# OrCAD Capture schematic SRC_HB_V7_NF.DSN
size A3; title: LMG3410R150; rev: 1.0; note: *
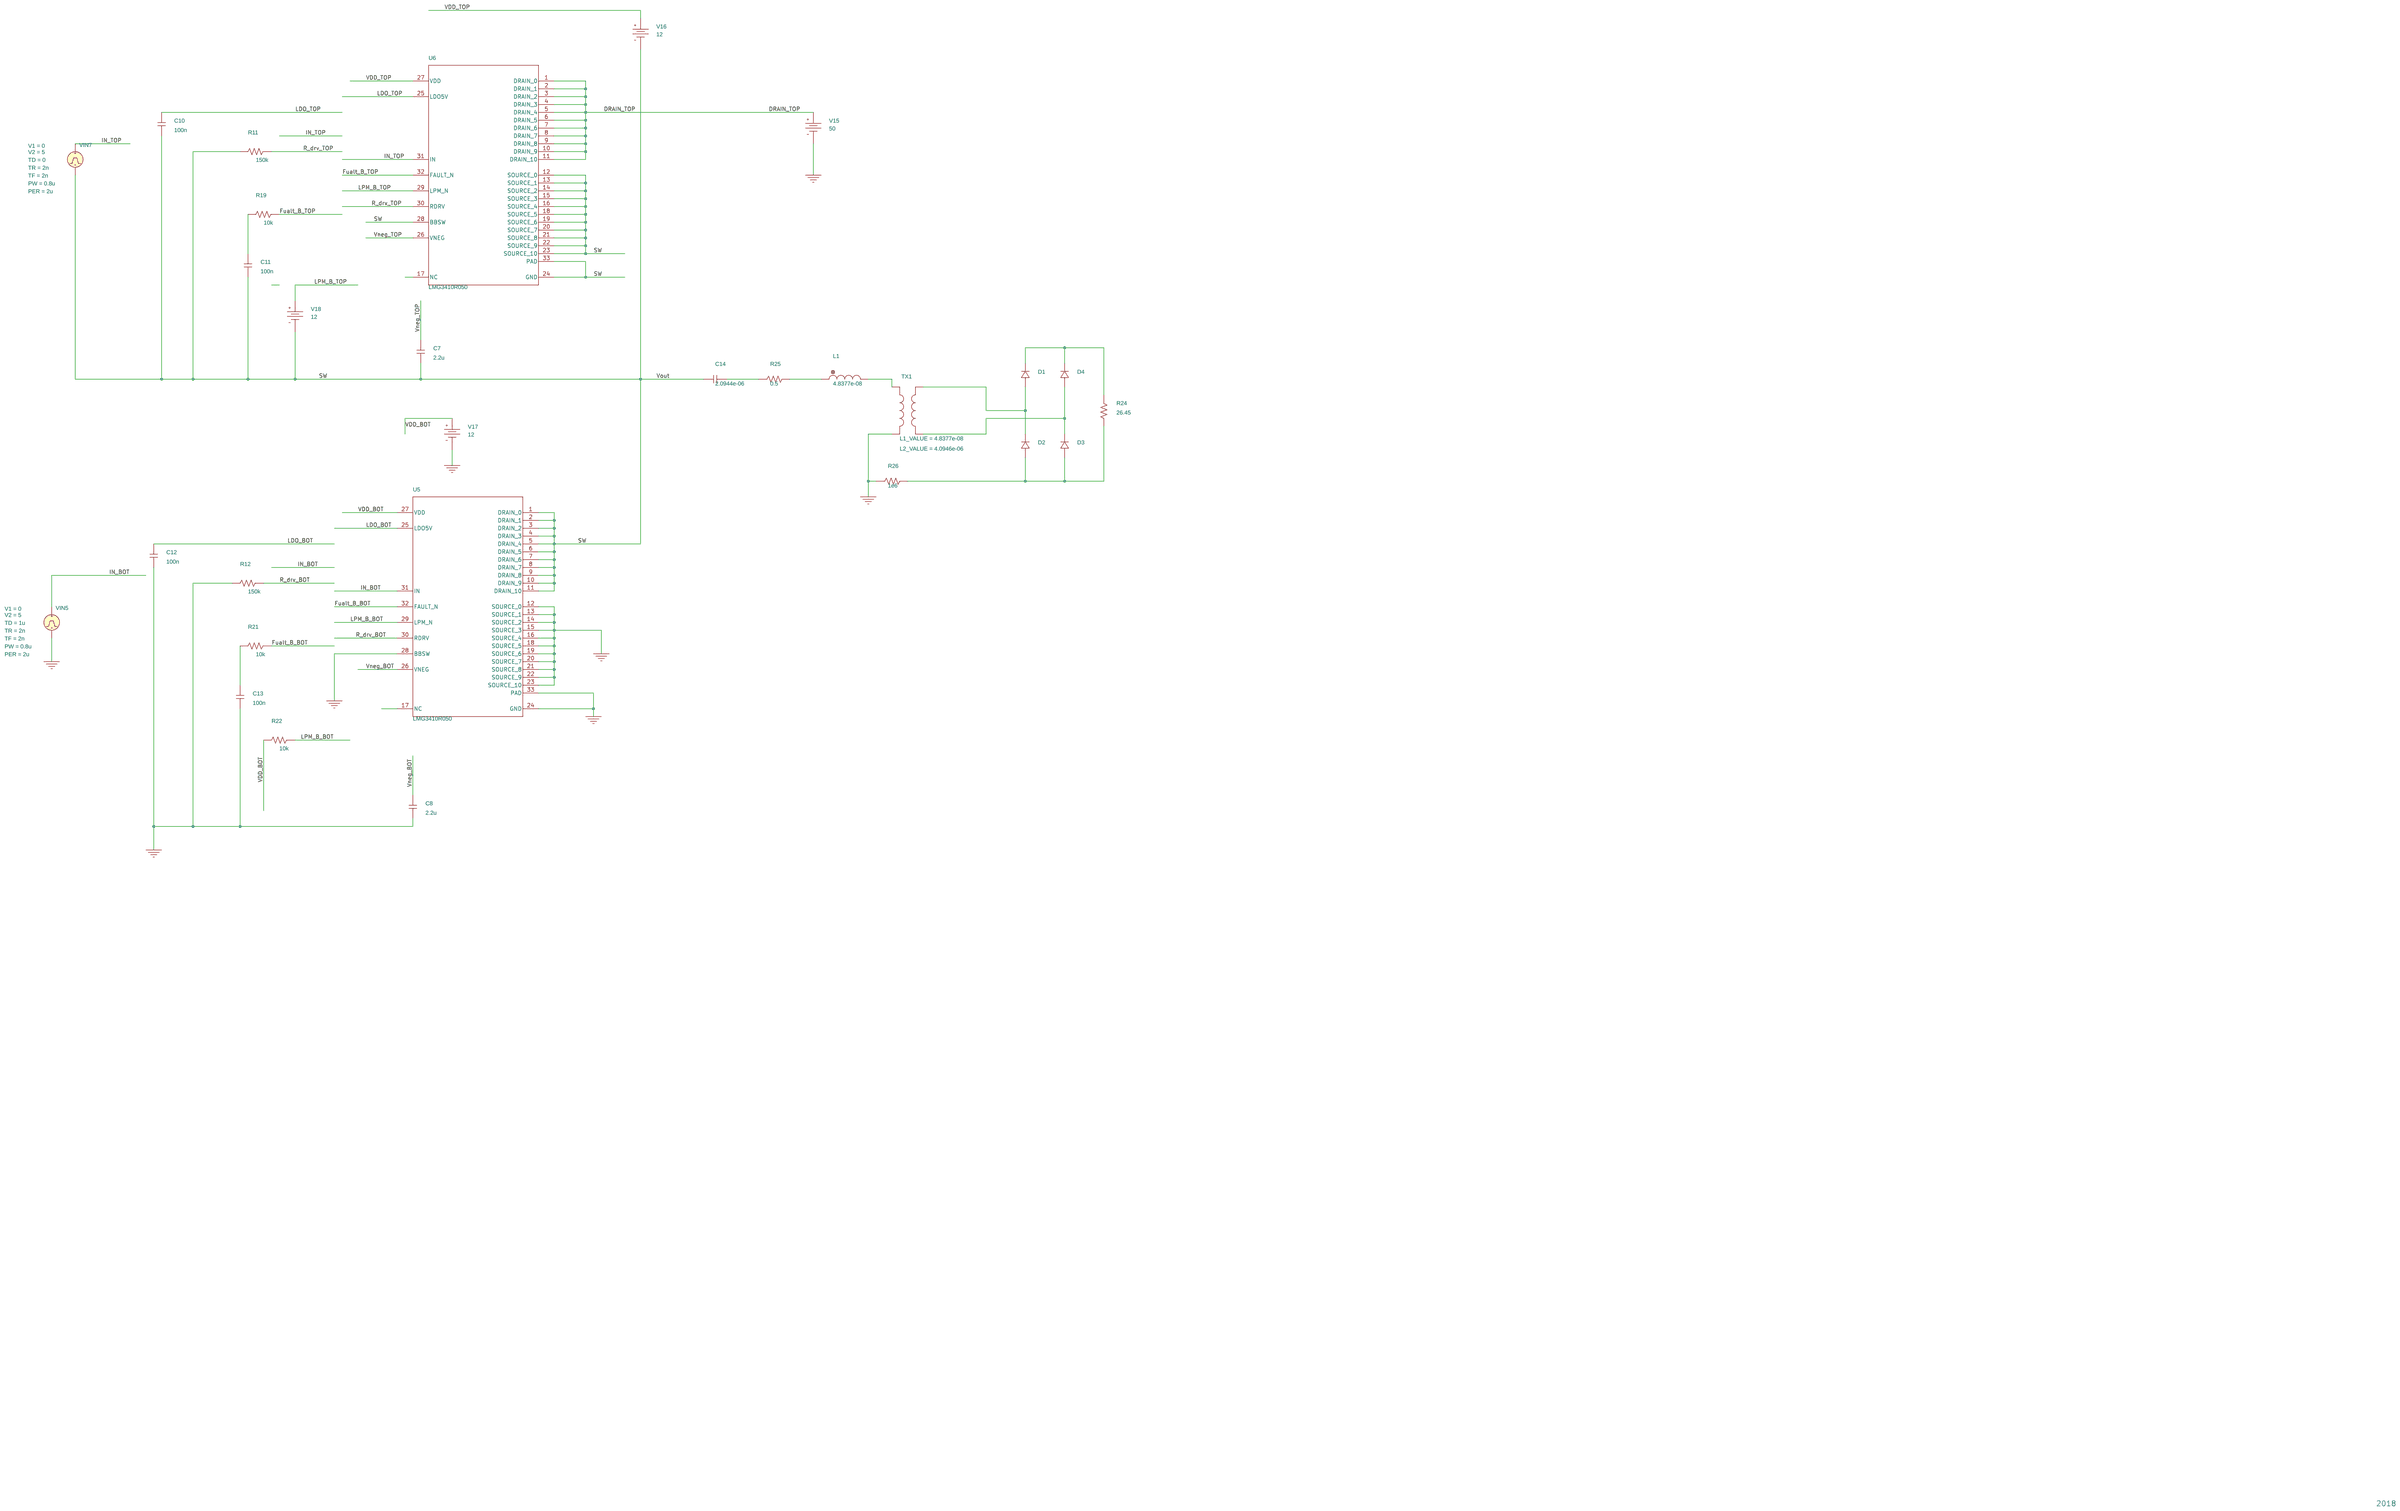
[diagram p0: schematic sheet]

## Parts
C7  2.2u  [RAD/CK05]
C8  2.2u  [RAD/CK05]
C10  100n  [RAD/CK05]
C11  100n  [RAD/CK05]
C12  100n  [RAD/CK05]
C13  100n  [RAD/CK05]
C14  2.0944e-06  [RAD/CK05]
D1  Dbreak
D2  Dbreak
D3  Dbreak
D4  Dbreak
L1  4.8377e-08  [DISC/.350x.175/LS.200x.100/.034]
R11  150k  [AX/RC05]
R12  150k  [AX/RC05]
R19  10k  [AX/RC05]
R21  10k  [AX/RC05]
R22  10k  [AX/RC05]
R24  26.45  [AX/RC05]
R25  0.5  [AX/RC05]
R26  1e6  [AX/RC05]
TX1  XFRM_LINEAR
U5  LMG3410R050  [RWH0032A]
U6  LMG3410R050  [RWH0032A]
V15  VDC
V16  VDC
V17  VDC
V18  VDC
VIN5  VPULSE
VIN7  VPULSE

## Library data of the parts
C7 C8 C10-C14 = C
D1-D4 = Dbreak
L1 = L
R11 R12 R19 R21 R22 R24-R26 = R
TX1 = XFRM_LINEAR: L1_VALUE: 4.8377e-08; L2_VALUE: 4.0946e-06
U5 U6 = LMG3410R050: Testbenches: [{"TestbenchDisplayName": "LMG3410R050 PSpice unencrypted model", "TestbenchURL": "https://software-dl.ti.com/pspice/esd/models/lmg3410r050_V1.0.zip", "TestbenchOpj": "LMG3410R050/lmg3410r050.opj"}]; Version: 1; productURL: http://www.ti.com/document-viewer/LMG3410R050/datasheet/
V15 = VDC: DC: 50
V16-V18 = VDC: DC: 12
VIN5 = VPULSE: PER: 2u; PW: 0.8u; TD: 1u; TF: 2n; TR: 2n; V1: 0; V2: 5
VIN7 = VPULSE: PER: 2u; PW: 0.8u; TD: 0; TF: 2n; TR: 2n; V1: 0; V2: 5

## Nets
VDD_BOT: R22.2 U5.27(VDD) V17.0(+)
VDD_TOP: U6.27(VDD) V16.0(+)
0: C8.1 C12.1 C13.1 R12.2 R26.1 TX1.2 U5.12(SOURCE_0) U5.13(SOURCE_1) U5.14(SOURCE_2) U5.15(SOURCE_3) U5.16(SOURCE_4) U5.18(SOURCE_5) U5.19(SOURCE_6) U5.20(SOURCE_7) U5.21(SOURCE_8) U5.22(SOURCE_9) U5.23(SOURCE_10) U5.24(GND) U5.28(BBSW) U5.33(PAD) V15.1(-) V17.1(-) VIN5.2(-)
DRAIN_TOP: U6.1(DRAIN_0) U6.2(DRAIN_1) U6.3(DRAIN_2) U6.4(DRAIN_3) U6.5(DRAIN_4) U6.6(DRAIN_5) U6.7(DRAIN_6) U6.8(DRAIN_7) U6.9(DRAIN_8) U6.10(DRAIN_9) U6.11(DRAIN_10) V15.0(+)
Fualt_B_BOT: R21.1 U5.32(FAULT_N)
Fualt_B_TOP: R19.1 U6.32(FAULT_N)
IN_BOT: U5.31(IN) VIN5.1(+)
IN_TOP: U6.31(IN) VIN7.1(+)
LDO_BOT: C12.2 U5.25(LDO5V)
LDO_TOP: C10.2 U6.25(LDO5V)
LPM_B_BOT: R22.1 U5.29(LPM_N)
LPM_B_TOP: U6.29(LPM_N) V18.0(+)
R_drv_BOT: R12.1 U5.30(RDRV)
R_drv_TOP: R11.1 U6.30(RDRV)
SW: C7.1 C10.1 C11.1 C14.1 R11.2 U5.1(DRAIN_0) U5.2(DRAIN_1) U5.3(DRAIN_2) U5.4(DRAIN_3) U5.5(DRAIN_4) U5.6(DRAIN_5) U5.7(DRAIN_6) U5.8(DRAIN_7) U5.9(DRAIN_8) U5.10(DRAIN_9) U5.11(DRAIN_10) U6.12(SOURCE_0) U6.13(SOURCE_1) U6.14(SOURCE_2) U6.15(SOURCE_3) U6.16(SOURCE_4) U6.18(SOURCE_5) U6.19(SOURCE_6) U6.20(SOURCE_7) U6.21(SOURCE_8) U6.22(SOURCE_9) U6.23(SOURCE_10) U6.24(GND) U6.28(BBSW) U6.33(PAD) V16.1(-) V18.1(-) VIN7.2(-)
Vneg_BOT: C8.2 U5.26(VNEG)
Vneg_TOP: C7.2 U6.26(VNEG)
N14584084: C13.2 R21.2
N14584296: C11.2 R19.2
N14681239: L1.2 TX1.1
N14681253: D1.1(2) D4.1(2) R24.1
N14681299: D2.0(1) D3.0(1) R24.2 R26.2
N14690204: D3.1(2) D4.0(1) TX1.4
N14696105: D1.0(1) D2.1(2) TX1.3
N14704108: C14.2 R25.1
N14704112: L1.1 R25.2

Not connected (* = marked no-connect by the designer): U5 17(NC); U6 17(NC)

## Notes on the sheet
- 2018
